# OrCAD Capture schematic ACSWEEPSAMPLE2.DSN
size A
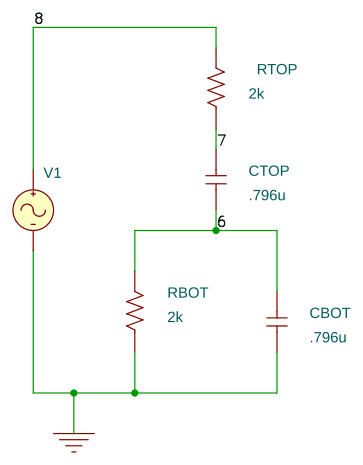
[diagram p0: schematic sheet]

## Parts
CBOT  .796u  [RAD/CK05]
CTOP  .796u  [RAD/CK05]
RBOT  2k  [AX/RC05]
RTOP  2k  [AX/RC05]
V1  VAC

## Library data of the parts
CBOT CTOP = C
RBOT RTOP = R
V1 = VAC

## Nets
0: CBOT.1 RBOT.1 V1.2(-)
6: CBOT.2 CTOP.1 RBOT.2
7: CTOP.2 RTOP.1
8: RTOP.2 V1.1(+)
